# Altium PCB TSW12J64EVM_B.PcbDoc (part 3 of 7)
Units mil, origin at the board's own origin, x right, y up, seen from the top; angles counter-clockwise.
Board outline 8833 x 2680 mil, 10 copper layers (Top Layer L1, Gnd-Plane - L2, Signals - L3, Gnd-Plane - L4, Pwr Plane - L5, Signals - L6, Gnd-Plane - L7, Signals - L8, Gnd-Plane - L9, Bottom Layer - L10), stack 57.8 mil thick; 950 components, 533 nets, 2888 pads, 1732 vias.
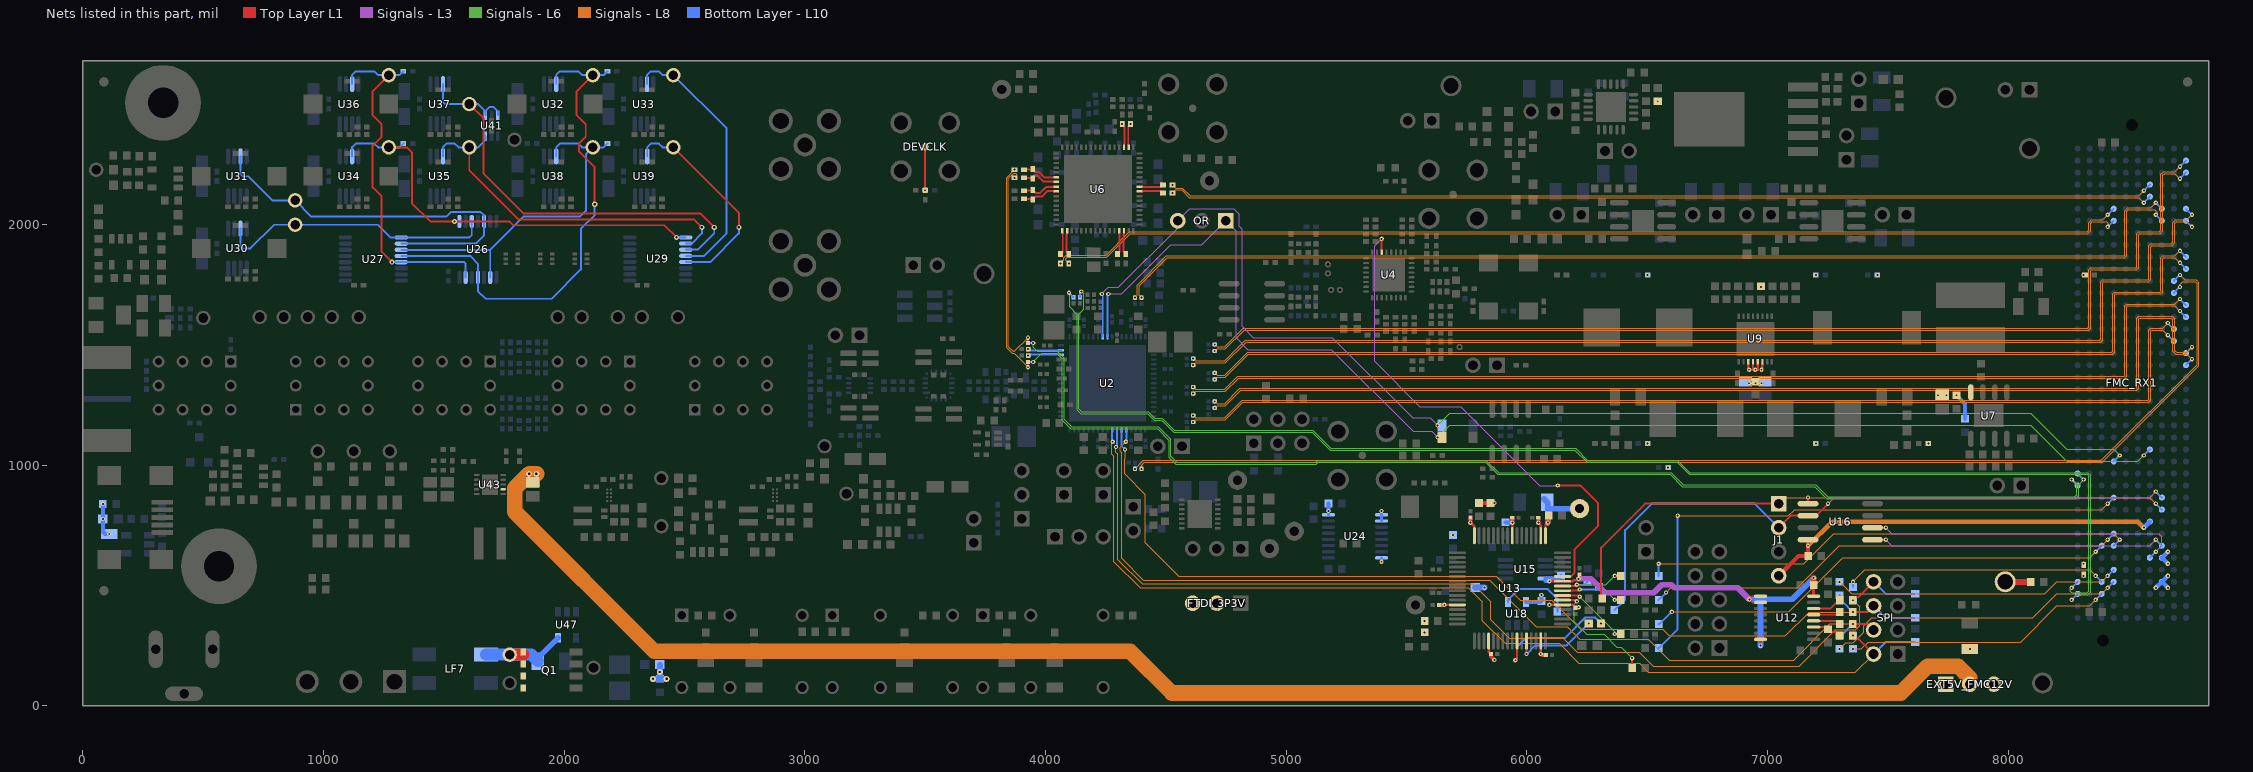
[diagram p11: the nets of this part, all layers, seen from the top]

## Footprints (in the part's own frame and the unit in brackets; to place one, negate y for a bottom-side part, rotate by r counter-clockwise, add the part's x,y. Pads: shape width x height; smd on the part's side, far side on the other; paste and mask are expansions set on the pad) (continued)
TSW-104-07-G-S [mm] "Samtec 100mil, 1x4, 230 mil above insulator"
  rect 1.65x1.65 hole 1.016 mask+0: 1(-3.81,0)
  round 1.65 hole 1.016 mask+0: 2(-1.27,0) 3(1.27,0) 4(3.81,0)
  silkscreen extent -6.1,-1.27 5.08,1.27, body extent -5.08,-1.27 5.08,1.27, height 8.38
VLS2012 [mm] "TDK"
  rect 0.65x2 smd: 1(-0.675,0) 2(0.675,0)
  silkscreen extent -0.15,-1.15 0.15,1.15, body extent -1.05,-1.05 1.05,1.05, height 1.2
WE-HC6 [mm] "Wurth Electronik recommended land pattern"
  rect 3.85x4 smd: 1(-3.825,0) 2(3.825,0)
  silkscreen extent -6.2,-6.2 6.2,6.2, body extent -5.77,-5.37 5.75,5.35, height 5
XFL4020 [mm] "Coilcraft XFL4020 7/18/12"
  rect 0.98x3.4 smd: 1(-1.181,0) 2(1.181,0)
  silkscreen extent -2.16,-2.16 2.16,2.16, body extent -2.15,-2.15 2.15,2.15, height 2.1
XTAL_ABM3 [mm] "Abracon recommended land pattern 12.28.10"
  rect 1.9x2.4 smd: 1(-2.05,0) 2(2.05,0)
  silkscreen extent -2.67,-1.78 2.67,1.78, body extent -2.6,-1.7 2.6,1.7, height 1.3
YFX0008ADAC [mm] "WCSP, 8-Leads, Body 1.645x0.855mm, Pitch 0.4mm"
  round 0.23 smd paste-0.13 mask+0.038: A1(-0.2,0.6) A2(0.2,0.6) B1(-0.2,0.2) B2(0.2,0.2) C1(-0.2,-0.2) C2(0.2,-0.2) D1(-0.2,-0.6) D2(0.2,-0.6)
  silkscreen extent -0.7,0.81 -0.53,0.99, body extent -0.45,-0.84 0.45,0.84, height 0.68

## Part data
1:1 2:1 5:1 AC DC: "Switch, Tactile, SPST-NO, 0.05A, 12V, SMD"
"1:1 Atten" "2:1 Atten" "5:1 Atten" 12V "AC COUPLED" "DC COUPLED" LD Status1 Status2 USB_PWR: "LED, Green, SMD"
1P8USB 3P3USB +5 +5V DPDT_1A DPDT_1B DPDT_2A DPDT_2B DPDT_3A DPDT_3B DPDT_4A DPDT_4B DPDT_5A DPDT_5B GND4 K1_Ax K1_Bx K2_Ax K2_Bx K3_Ax K3_Bx K4_Ax K4_Bx K5_Ax K5_Bx LD1 LD2 LO2_N LO2_P LO3_N LO3_P OFFSET TCRIT1 TCRIT2 TCRIT3 TP41_4 VIO_3P75_U19 VIO_3P75_U23 VIO_5V_DRV VIO_5V_LMC VIO_5V_LMH VIO_5V_LOGIC VIO_-1P25_U19 VIO_-1P25_U23 Vtune: "TEST POINT.  No entry in BOM."
1V2ADC_INT 1V2ADC_LDO 1V9ADC 1V9INT "5401 PD" "6401 PD" EXT_Vcmo J2 J3 "KC705 JTAG" LMK_INT LMK_LDO LMX_INT LMX_LDO PG_RX1 Tdiode VA12 VA19 Vbg VD12: "Header, TH, 100mil, 2x1, Gold plated, 230 mil above insulator"
3P3RX GND GND1 GND2 GND3 VADJ_RX: "Test Point, TH, Multipurpose, Black"
5VDC: "Connector, DC Jack 2.1X5.5 mm, TH"
C1 C77 C79 C239 C242 C253 C256 C272 C309: "CAP, CERM, 0.01uF, 25V, +/-10%, X7R, 0402"
C2 C8 C11 C94 C95 C96 C215 C216 C217 C218 C219 C220 C221 C222 C223 C224 C225 C226 C227 C261: "CAP, CERM, 0.1uF, 10V, +/-10%, X7R, 0402"
C3 C275: "CAP, TA, 10uF, 10V, +/-10%, 0.9 ohm, SMD"
C4 C5 C18 C19 C73 C85 C86 C87 C88 C89 C100 C103 C104 C105 C106 C107 C109 C110 C111 C112 C113 C114 C120 C121 C123 C124 C206 C207 C208 C209 C231 C235 C250 C251 C258 C259 C260 C273 C274 C295 C296 C310 C321 C322 C323 C324 C325 C326 C327 C328 C329 C330 C331 C332 C333 C334 C335 C336 C337 C338 C339 C340 C346 C347 C349 C350 C351 C352 C353 C354 C355 C384: "CAP, CERM, 0.1uF, 10V, +/-10%, X5R, 0402"
C7 C9 C10 C12 C13 C14 C15 C17 C20 C21 C22 C23 C26 C28 C29 C31 C41 C42 C43 C44 C45 C46 C47 C51 C52 C53 C54 C55 C56 C57 C58 C62 C63 C64 C65 C66 C67 C68 C69 C70 C71 C118 C119 C131 C132 C133 C134 C136 C140 C142 C214: library part Capacitor, "CAP, CERM, 0.1uF, 6.3V, X5R, 10%, 0201"
C16: "CAP, CERM, 4.7uF, 6.3V, +/-20%, X5R, 0402"
C24 C115 C210: "CAP, CERM, 0.1uF, 16V, +/-5%, X7R, 0603"
C25 C34 C38: "CAP, CERM, 100pF, 50V, +/-5%, C0G/NP0, 0603"
C27 C48 C59 C72: "CAP, TANT, 10uF, 10V, +/-20%, 2.5 ohm, 3528-21 SMD"
C30 C36: "CAP, CERM, 0.22uF, 6.3V, +/-20%, X5R, 0201"
C32 C33 C35 C37 C90 C91 C92 C93 C262 C263: "CAP, CERM, 4700pF, 10V, +/-10%, X5R, 0201"
C39 C40 C49 C50 C60 C61 C99 C125 C143 C205: "CAP, CERM, 1uF, 10V, +/-10%, X5R, 0603"
C74: "CAP, CERM, 100pF, 25V, +/-5%, C0G/NP0, 0402"
C75 C76 C83 C84 C245: "CAP, CERM, 47pF, 50V, +/-5%, C0G/NP0, 0402"
C78 C80 C254 C257: "CAP, CERM, 27pF, 50V, +/-5%, C0G/NP0, 0402"
C81 C82 C232 C236 C240 C243 C252 C255: "CAP, CERM, 1uF, 6.3V, +/-20%, X5R, 0402"
C97 C98 C116 C126 C129 C130 C144 C147 C148 C151 C153 C159 C164 C167 C176 C177 C185 C189 C191 C198 C199 C213 C277 C281 C283 C288 C290 C298 C300 C357 C359 C390 C392 C393 C396 C399 C402 C405 C407 C411 C416: "CAP, CERM, 0.1uF, 25V, +/-5%, X7R, 0603"
C102 C311 C312 C313 C314 C315 C316 C317 C318 C319 C320: "CAP, CERM, 0.01uF, 16V, +/-10%, X7R, 0402"
C108 C155 C201 C211: "CAP, CERM, 1uF, 16V, +/-10%, X5R, 0603"
C117 C149: "CAP, CERM, 330pF, 50V, +/-5%, C0G/NP0, 0603"
C122: "CAP, CERM, 10uF, 10V, +/-10%, X5R, 0805"
C127 C160: "CAP, CERM, 4.7uF, 10V, +/-10%, X5R, 0603"
C128 C161 C278 C408: "CAP, CERM, 0.01uF, 100V, +/-20%, X7R, 0603"
C135 C137: "CAP, CERM, 18pF, 50V, +/-5%, C0G/NP0, 0402"
C138 C212: "CAP, CERM, 100uF, 6.3V, +/-20%, X5R, 1206"
C139 C141 C150 C152 C158 C163 C165 C166 C171 C172 C186 C188 C190 C194 C195 C196 C197 C200 C202 C203 C204 C276 C280 C282 C289 C297 C299 C358 C391 C395 C398 C401 C404 C406 C410 C415: "CAP, CERM, 10uF, 10V, +/-10%, C0G/NP0, 0603"
C145 C146 C173 C184 C382 C383: "CAP, CERM, 10uF, 16V, +/-10%, X5R, 0805"
C154: "CAP, CERM, 10pF, 50V, +/-5%, C0G/NP0, 0603"
C156 C157: "CAP, CERM, 47uF, 6.3V, +/-20%, X5R, 1206"
C162: "CAP, CERM, 3300pF, 25V, +/-10%, X7R, 0603"
C168: "CAP, CERM, 0.22uF, 16V, +/-10%, X7R, 0603"
C169 C170: "CAP, CERM, 0.1uF, 6.3V, +/-10%, X5R, 0402"
C174 C175: "CAP, CERM, 0.027uF, 16V, +/-10%, X7R, 0603"
C178 C179: "CAP, CERM, 0.039uF, 25V, +/-10%, X7R, 0603"
C180 C181 C182 C183: "CAP, CERM, 22uF, 10V, +/-20%, X5R, 1206"
C187: "CAP, CERM, 560pF, 50V, +/-5%, C0G/NP0, 0603"
C192: "CAP, CERM, 4700pF, 16V, +/-10%, X7R, 0603"
C193: "CAP, TA, 47 µF, 10 V, +/- 10%, 0.25 ohm, SMD"
C228 C229: library part GRM155R71A104KA01D, "CAP CER 0.5PF 50V NP0 0402"
C230 C234 LF2: "CAP, CERM, 47pF, 50V, +/-5%, C0G/NP0, 0603"
C233 C237 C238 C241 C246 C248: "CAP, CERM, 4.7pF, 50V, +/-5%, C0G/NP0, 0402"
C244: "CAP, CERM, 560pF, 50V, +/-5%, C0G/NP0, 0402"
C247: "CAP, CERM, 2.2pF, 50V, +/-5%, C0G/NP0, 0402"
C249: "CAP, CERM, 22pF, 50V, +/-5%, C0G/NP0, 0402"
C264 C265 C270 C271 C301 C302 C307 C308: "CAP, CERM, 0.01uF, 25V, +/-20%, X7R, 0306"
C266 C267 C268 C269 C303 C304 C305 C306: "CAP, CERM, 2200pF, 50V, +/-20%, X7R, 0306"
C279: "CAP, CERM, 15 pF, 50 V, +/- 5%, C0G/NP0, 0603"
C284 C285 C418 C419: "CAP, CERM, 22 µF, 6.3 V, +/- 20%, X5R, 0603"
C286 C385 C417: "CAP, CERM, 10 pF, 50 V, +/- 5%, C0G/NP0, 0402"
C287 C356 C389: "CAP, CERM, 2.2 µF, 10 V, +/- 10%, X5R, 0603"
C291 C292: "CAP, CERM, 1 pF, 50 V, +/- 5%, C0G/NP0, 0402"
C293 C294: "CAP, CERM, 2.4 pF, 50 V, +/- 5%, C0G/NP0, 0402"
C341 C342 C343 C344 C345: "CAP, CERM, 1000 pF, 25 V, +/- 5%, C0G/NP0, 0402"
C360 C361 C362 C363 C364 C365 C366 C367 C368 C369 C413 C414: "CAP, TA, 1 µF, 16 V, +/- 20%, 9.3 ohm, SMD"
C370 C371 C372 C373 C374 C375 C376 C377 C378 C379 C380 C381 C403: library part Capacitor, "CAP, CERM, xxxF, xxV, [TempCo], xx%, [PackageReference]"
C386 C387 C388 C394 C397 C400: "CAP, CERM, 22 µF, 16 V, +/- 10%, X5R, 0805"
C409: "CAP, CERM, 22 pF, 50 V, +/- 5%, C0G/NP0, 0603"
D1 D7: "Diode, Schottky, 30 V, 0.5 A, SOD882"
D2 D4: "Diode, Ultrafast, 100V, 0.15A, SOD-123"
D3: "Diode, Dual Switching, Series, 10-mA, 7V"
D5 D6: "Diode, Schottky, 40V, 5A, SMC"
DEVCLK EXT_VCO LMKCLK OSCin: "Connector, SMA,Vertical, Thru hole w/SMT center pin"
EXT5V_FMC12V: "Header, TH, 100mil, 1x3, Gold plated, 230 mil above insulator"
F1: "Fuse, 2 A, 63 V, SMD"
FID1 FID2 FID3: "Fiducial mark.  There is nothing to buy or mount."
FL1 FL2 FL3: "Filter, LC, 0.2uF, 1806, SMT"
FMC_RX1: "Connector, Receptacle, 400-Pos (40x10), 50x50-mil Pitch, SMT"
FTDI_3P3V OR RSV "Ts ADD1" Vcmo: "Header, TH, 100mil, 3x1, Gold plated, 230 mil above insulator"
H3 H4: library part 1902C, "Standoff, Round, 3/16\"  x 1-3/16\"L #4-40 Aluminum"
H5 H6: "Machine Screw, Round, #4-40 x 1/4, Nylon, Philips panhead"
J1: "Header, TH, 100mil, 4x1, Gold plated, 230 mil above insulator"
K1 K2 K3 K4 K5: "Relay, DPDT (2 Form C), , 5 VDC, TH, K1 - K5 Body to be mounted approxiamtely 0.025 inches above PC board but cannot be in contact with the PC board"
K6 K7: "Relay, SPDT (1 Form C), 2A, 5 VDC, TH"
K8: "Relay, SPDT (1 Form C), 2 A, 5 VDC, TH"
L1 L27 L28 L29 L30 L31 L32 L33 L34: "0.25A Ferrite Bead, 1000 ohm @ 100MHz, SMD"
L2 L3 L4 L5 L19 L21 L22 L23: "1.5A Ferrite Bead, 330 ohm @ 100MHz, SMD"
L6 L9 L10 L13 L15 L16 L17 L18 L26: "6A Ferrite Bead, 26 ohm @ 100MHz, SMD"
L7 L14 L20 L24 L25 L35 L36 L40 L42 L43 L44 L45 L46 L47 L48 L50 L51 L52 L53 L54: "3A Ferrite Bead, 120 ohm @ 100MHz, SMD"
L8: "Inductor, Shielded Drum Core, Ferrite, 3uH, 3A, 0.024 ohm, SMD"
L11: "Inductor, Shielded Drum Core, Ferrite, 7uH, 4.35A, 0.03 ohm, SMD"
L12: "Inductor, Shielded Drum Core, Superflux, 5.5uH, 10A, 0.0112 ohm, SMD"
L37 L41: "Inductor, Shielded, Ferrite, 6.8 µH, 0.57 A, 0.498 ohm, SMD"
L38 L39: "Inductor, Wirewound, 5.6 nH, 0.9 A, 0.045 ohm, SMD"
L49: "Inductor, Shielded, Composite, 1 µH, 5.4 A, 0.01 ohm, SMD"
L55 L56: "Inductor, Wirewound, Ceramic, 3.9 nH, 2.2 A, 0.054 ohm, SMD"
LF1: "CAP, CERM, 3900pF, 25V, +/-5%, C0G/NP0, 0603"
LF3: "RES, 619 ohm, 1%, 0.1W, 0603"
LF7: "Coupled inductor, 5A, 0.01 ohm, SMD"
Logo1: library part ESD_Susceptible, "ESD Susceptible Symbol"
Logo2: library part TI_Logo, "Texas Instrument Corporate Signature"
Logo3: library part Pb-Free
Logo4: library part FCC_disclaimer, "FCC_disclaimer"
LOGO5: library part IEC_HotSurface, "IEC 61010-1 Hot Surface Warning"
NCO: "Header, TH, 100mil, 3x2, Gold plated, 230 mil above insulator"
"OFFSET ADJ": "Trimmer, 1k, 0.25W, SMT"
OR_T0 OR_T1: "LED, Orange, SMD"
Q1: "MOSFET, N-CH, 60 V, 172 A, SON 5x6mm"
Q2 Q3 Q4: "MOSFET, P-CH, 20 V, 0.83 A, SOT-563"
R1: "RES, 8.06k ohm, 1%, 0.063W, 0402"
R2 R10: "RES, 1.2k ohm, 5%, 0.063W, 0402"
R3 R11 R150 R243 R245: "RES, 1.0Meg ohm, 5%, 0.063W, 0402"
R4 R5 R6 R14 R15 R16 R105 R106 R107 R123 R130 R131 R187: "RES, 10.0k ohm, 1%, 0.1W, 0603"
R7 R8 R9 R18 R19 R20 R21 R22 R23: "RES, 0 ohm, 5%, 0.05W, 0201"
R12: "RES, 1.33k ohm, 1%, 0.063W, 0402"
R13: "RES, 3.30k ohm, 0.1%, 0.1W, 0603"
R17: "RES, 750 ohm, 5%, 0.1W, 0603"
R24 R144 R190 R234 R235 R236 R237 R238: "RES, 10.0k ohm, 1%, 0.063W, 0402"
R25 R26 R29 R36 R38 R43 R44 R48 R59 R60 R61 R62 R63 R64 R145 R146 R147 R148 R149 R160 R161 R178 R181 R233: "RES, 0 ohm, 5%, 0.063W, 0402"
R27 R28 R34 R35: "RES, 100 ohm, 1%, 0.063W, 0402"
R30 R153 R229 R230: "RES, 49.9 ohm, 1%, 0.063W, 0402"
R31 R32 R122: "RES, 1.3k ohm, 5%, 0.1W, 0603"
R33 R37: "RES, 3.3k ohm, 5%, 0.063W, 0402"
R39 R71 R80 R134: "RES, 1.0k ohm, 5%, 0.1W, 0603"
R40 R42 R73 R75 R83 R84 R92 R95: "RES, 0.002 ohm, 1%, 1W, 1206"
R41 R74: "RES, 10.7k ohm, 1%, 0.1W, 0603"
R45 R56 R112: "RES, 270 ohm, 5%, 0.1W, 0603"
R47: "RES, 2.32k ohm, 1%, 0.1W, 0603"
R49 R77: "RES, 4.64k ohm, 1%, 0.1W, 0603"
R50 R239 R240 R241: library part Resistor, "RES, xxx ohm, x%, xW, [PackageReference]"
R51 R165: "RES, 51 ohm, 5%, 0.063W, 0402"
R52 R53: "RES, 10 ohm, 5%, 0.1W, 0603"
R54 R55 R57 R58 R65 R68 R69 R109 R110 R111 R113 R114 R115 R117 R118 R119 R120 R121 R124 R125 R126 R127 R186: "RES, 100 ohm, 5%, 0.1W, 0603"
R66 R93: "RES, 1.00k ohm, 1%, 0.1W, 0603"
R67: "RES, 12.0k ohm, 1%, 0.1W, 0603"
R70: "RES, 10k ohm, 5%, 0.1W, 0603"
R72 R177: "RES, 95.3 k, 1%, 0.1 W, 0603"
R76: "RES, 22.1k ohm, 1%, 0.1W, 0603"
R78: "RES, 10.0 ohm, 1%, 0.1W, 0603"
R79: "RES, 732 ohm, 1%, 0.1W, 0603"
R81: "RES, 16.2k ohm, 1%, 0.1W, 0603"
R82: "RES, 7.87k ohm, 1%, 0.1W, 0603"
R85: "RES, 2.49k ohm, 1%, 0.1W, 0603"
R86 R87: "RES, 5.90k ohm, 1%, 0.1W, 0603"
R88 RR6: "RES, 4.99k ohm, 1%, 0.1W, 0603"
R89: "RES, 2.80k ohm, 1%, 0.1W, 0603"
R90: "RES, 402 ohm, 1%, 0.1W, 0603"
R91: "RES, 4.99k ohm, 1%, 0.063W, 0402"
R94 R251 R252 R253 R254 R255: "RES, 1.0k ohm, 5%, 0.25W, 1206"
R96: "RES, 357 ohm, 1%, 0.1W, 0603"
R97 R98 R101 R102: "RES, 12.4k ohm, 1%, 0.1W, 0603"
R99 R100 R103 R132 R142 R143 R151 R152 R259 R260 R261 R262 R263 R264 RR7: "RES, 0 ohm, 5%, 0.1W, 0603"
R104 R116 R128 R129: "RES, 24k ohm, 5%, 0.063W, 0402"
R108: "RES, 2.2k ohm, 5%, 0.1W, 0603"
R133 R170 R173 R242 R250 R256: "RES, 1.00k ohm, 1%, 0.063W, 0402"
R135: "RES, 2.10k ohm, 1%, 0.1W, 0603"
R136 R137 R138: "RES, 4.7k ohm, 5%, 0.1W, 0603"
R139 R140 R141: "RES, 2.0k ohm, 5%, 0.1W, 0603"
R154: "RES, 261, 1%, 0.063 W, 0402"
R156 R157: "RES, 127 ohm, 1%, 0.063W, 0402"
R158 R159: "RES, 82.5 ohm, 1%, 0.063W, 0402"
R162: "RES, 107 ohm, 1%, 0.063W, 0402"
R163 R164: "RES, 2.2k ohm, 5%, 0.063W, 0402"
R166 R167: "RES, 560, 5%, 0.063 W, 0402"
R168 R204: "RES, 365, 1%, 0.063 W, 0402"
R169 R203: "RES, 22.6, 1%, 0.063 W, 0402"
R171: "RES, 62.0 k, 1%, 0.1 W, 0603"
R172 R249: "RES, 30.1 k, 1%, 0.1 W, 0603"
R174 R257: "RES, 274 k, 1%, 0.063 W, 0402"
R175 R213 R214 R215 R216 R217 R218 R219 R220 R221 R222 R258: "RES, 100 k, 1%, 0.063 W, 0402"
R176: "RES, 5.23 k, 1%, 0.1 W, 0603"
R179 R180: "RES, 4.99, 1%, 0.063 W, 0402"
R182 R183 R188 R189: "RES, 2.00 k, 1%, 0.063 W, 0402"
R184 R185: "RES, 1.21 k, 1%, 0.063 W, 0402"
R191 R193 R200 R202: library part CRCW0402150RFKED, "RES, 150, 0.1%, 0.063 W, 0402"
R192 R201: library part CRCW040237R4FKED, "RES, 37.4, 0.1%, 0.063 W, 0402"
R194 R196 R197 R199: library part CRCW040275R0FKED, "RES, 75.0, 0.1%, 0.063 W, 0402"
R195 R198: library part CRCW0402121RFKED, "RES, 121, 0.1%, 0.063 W, 0402"
R205 R206: "RES, 15.0, 1%, 0.063 W, 0402"
R207 R208: "RES, 0, 5%, 0.063 W, 0402"
R209 R210: "RES, 127, 1%, 0.063 W, 0402"
R211 R212: "RES, 40.2 ohm, 1%, 0.063W, 0402"
R224 R225 R226 R227 R228: "RES, 10.0 k, 1%, 0.063 W, 0402"
R231: "RES, 60.4 k, 1%, 0.1 W, 0603"
R232: "RES, 39.2 k, 1%, 0.1 W, 0603"
R244: "RES, 110 k, 1%, 0.063 W, 0402"
R246: "RES, 80.6 k, 1%, 0.1 W, 0603"
R247: "RES, 25.5 k, 1%, 0.1 W, 0603"
R248: "RES, 43.2 k, 1%, 0.1 W, 0603"
S1: "SWITCH SLIDE SPST 4A PCB, TH"
SH-1V2ADC_INT_1_2 SH-1V2ADC_LDO_1_2 SH-1V9ADC_1_2 SH-1V9INT_1_2 SH-EXT5V_FMC12V_1_2 SH-FTDI_3P3V_1_2 SH-J2_1_2 SH-LMK_INT_1_2 SH-LMK_LDO_1_2 SH-LMX_INT_1_2 SH-LMX_LDO_1_2 SH-RSV_1_2 "SH-Ts ADD1_1_2" Vcmo_2_3: "Shunt, 100mil, Gold plated, Black"
SPI: "Header, TH, 100mil, 4x2, Gold plated, 230 mil above insulator"
T2: "Transformer, RF, 50 ohm, 10 to 4000 MHz, SMT"
TEMP: "LED, Red, SMD"
TMST+ TMST-: "Connector, TH, SMA"
U1: library part LMC6762AIMX, "Dual Micro-Power Rail-to-Rail Input CMOS Comparator with Push-Pull Output, 8-pin Narrow SOIC"
U2: library part ADC12X3500RFLQNOPB, "ADC12J4000RLY Ultra-Wideband RF Sampling Subsystem, RLY0068A"
U3: "Dual Remote Diode and Local Temperature Sensor with SMBus Interface and TruTherm Technology, 14-pin LLP, Pb-Free"
U4: "Integer-N/Fractional-N PLL with Integrated VCO, RHB0032E"
U5 U8: "Micropower 800mA Low Noise \"Ceramic Stable\" Adjustable Voltage Regulator for 1V to 5V Applications, 8-pin PSOP, Pb-Free"
U6: "Low-Noise Clock Jitter Cleaner with Dual Loop PLLs, NKD0064A"
U7: "3-A OUTPUT SINGLE SYNCRONOUS STEP DOWN SWITCHER WITH INTEGRATED FET(SWIFT), DDA0008B"
U9: "Dual 2A, 500kHz Wide Input Range Buck Regulator, 16-pin LLP, Pb-Free"
U10: "3.0A Low Dropout Linear Regulator with Programmable Soft-Start, RGW0020A"
U11: "3A Fast-Transient Response Adjustable Low-Dropout Linear Voltage Regulator, 5-pin TO-263 Thin, Pb-Free"
U12 U24: "4-BIT DUAL-SUPPLY BUS TRANSCEIVER WITH CONFIGURABLE VOLTAGE TRANSLATION AND 3-STATE OUTPUTS, PW0016A"
U13: "Quad High Speed USB to Multipurpose UART/MPSSE IC"
U14: "300-mA, Low-IQ, Low-Dropout Regulator, DBV0005A"
U15: "1K, 64x16-bit, 2.5V Microwire Serial EEPROM, 8-Pin MSOP, Industrial Temperature"
U16: "64Kbit, 400kHz, 4.5V, I2C Serial EEPROM, 8-Pin SOIC 208mil, Commercial Temperature, Tape and Reel"
U17: "Divide-by-2 Divider"
U18: "IC, Single Bus Buffer Gate With 3-States Output"
U19: library part LMH5401RMS, "8GHz Ultra Wideband Fully Differential Amplifier, RMS0014A"
U20 U45: "Single Output High PSRR LDO, 200 mA, Adjustable 1.22 to 5.5 V Output, 2.7 to 5.5 V Input, 6-pin SOT-23 (DBV), -40 to 85 degC, Green (RoHS & no Sb/Br)"
U21 U48: "SIMPLE SWITCHER Buck-Boost Converter For Negative Output Voltage in uSMD, YFX0008ADAC"
U22 U42: "Single Output LDO, 200 mA, Adjustable -10 to -1.2 V Output, -10 to -2.7 V Input, 5-pin SOT-23 (DBV), -40 to 125 degC, Green (RoHS & no Sb/Br)"
U23: "5 GHz Ultra Wideband Digital Variable Gain Amplifier, RMZ0016A"
U25: "Precision, Low Noise, Low Iq Operational Amplifier, 2.2 to 5.5 V, -40 to 125 degC, 5-pin SOT23 (DCK0005A), Green (RoHS & no Sb/Br)"
U26: "High-Speed CMOS Logic Hex Inverting Schmitt Triggers, PW0014A"
U27 U29: "7- bit Integrated Motor and Relay Driver, PW0016A"
U30 U31 U32 U33 U34 U35 U36 U37 U38 U39: "CMOS Timer, 8-pin Mini SOIC, Pb-Free"
U40: "High-Speed, Closed-Loop Buffer, DBV0005A"
U41: "IC, Configurable Multiple-Function Gate"
U43: "High Input Voltage Buck-Boost Converter with 2 A Switch Current, DSC0010E"
U44: "Cap-Free, NMOS, 250mA Low Dropout Regulator with Reverse Current Protection, DBV0005A"
U47: "OVERVOLTAGE PROTECTION CONTROLLER, DBV0005A"
USB: "MINI USB 2.0 SMT TYPE AB 5 CONTACTS R/A, SMD"
uWIRE: "Connector, 100mil Shrouded, 5x2, High-Temperature, Gold, TH"
VIN: "Connector, SMT, End launch SMA 50 ohm"
Y1: "OSC 100.0000MHZ 3.3V +-25PPM SMD"
Y2: "Crystal, 12Mhz, 18pF, SMD"
ZZ2 ZZ3 ZZ4: library part AssemblyNote

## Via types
v1: diameter 18, hole 8, Top Layer L1 to Bottom Layer - L10, tented both sides, 1096 vias
v2: diameter 21.46, hole 10, Top Layer L1 to Bottom Layer - L10, tented both sides, 266 vias
v3: diameter 25, hole 10, Top Layer L1 to Bottom Layer - L10, tented both sides, 154 vias
v4: diameter 19.68, hole 7.87, Top Layer L1 to Bottom Layer - L10, 103 vias
v5: diameter 18, hole 8, Top Layer L1 to Bottom Layer - L10, tented bottom, 42 vias
v6: diameter 18, hole 8, Top Layer L1 to Bottom Layer - L10, tented top, 24 vias
v7: diameter 18, hole 8.01, Top Layer L1 to Bottom Layer - L10, tented both sides, 16 vias
v8: diameter 18, hole 8.01, Top Layer L1 to Bottom Layer - L10, tented bottom, 16 vias
v9: diameter 25.98, hole 12.99, Top Layer L1 to Bottom Layer - L10, tented top, 8 vias
v10: diameter 19.68, hole 7.87, Top Layer L1 to Bottom Layer - L10, tented top, 5 vias
v11: diameter 126, hole 106, Top Layer L1 to Bottom Layer - L10, tented top, 2 vias

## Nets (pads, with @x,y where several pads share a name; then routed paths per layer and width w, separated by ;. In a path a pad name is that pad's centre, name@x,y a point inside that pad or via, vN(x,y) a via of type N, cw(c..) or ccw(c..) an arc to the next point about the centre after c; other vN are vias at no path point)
1P8V_USB: 1P8USB.1 C133.1 C134.1 C136.1 C200.1 C212.2 U13.12 U13.37 U13.49 U13.64 | length 608
  Top Layer L1 w10: v1(5656.5,419.1) U13.12@5710.97,419.1 ; v1(5765,760.97) 5781.83,744.14 U13.64@5781.83,706.5 ; U13.49@6077.11,706.5 6077.11,751.13 v1(6086.95,760.97) ; v1(6093.51,419.1) U13.37@6147.98,419.1 6190.83,419.1 C134.1@6202.44,407.49 6204.22,409.26 v1(6215,409.26)
  Top Layer L1 w16.5: C133.1@5635.44,419.1 v1(5656.5,419.1) ; v1(5765,760.97) C136.1@5765,782.03
  Top Layer L1 w24: v1(6086.95,760.97) 6086.95,785.96 C200.1@6090.7,789.7
  Bottom Layer - L10 w24: C212.2@6070,860.09 C212.2@6084.09,846 ; v1(6086.95,760.97) C212.2@6086.95,843.13 ; C212.2@6086.95,819 1P8USB.1@6219,819
3P3V_FTDI: C97.1 C118.1 C119.1 C129.1 C131.1 C132.1 C205.1 C213.1 C214.1 FTDI_3P3V.2 L24.1 L25.1 R66.2 R105.2 R106.2 R107.2 U12.1 U12.2 U12.8 U12.16 U13.20 U13.31 U13.42 U13.50 U13.56 U15.8 U18.5 U24.1 U24.2 U24.8 U24.16 USB_PWR.1 | length 2364.2
  Top Layer L1 w8: U12.2@6970.76,429.5 6936.79,429.5 v1(6924,442.3) 6936.8,455.1 U12.1@6970.76,455.1
  Top Layer L1 w10: U13.20@5840.89,269.5 5840.89,224.87 C118.1@5850.73,215.03 ; U13.56@5939.31,706.5 v1(5939.31,760.97) ; v1(6047.58,760.97) 6057.42,751.13 U13.50@6057.42,706.5 ; v1(6057.43,215.03) U13.31@6057.42,269.5 ; v1(6093.51,517.53) U13.42@6147.98,517.53 6190.83,517.53 6194.14,520.84 6208.47,520.84 v1(6215,527.37)
  Top Layer L1 w13: v1(6970.76,250) U12.8@6970.76,275.96 ; U12.16@7191.24,455.1 C129.1@7191.24,502.06
  Top Layer L1 w16: v1(6215,527.37) 6218.44,530.82 C131.1@6218.44,545.43
  Top Layer L1 w16.5: R107.2@5800.2,842.56 v1(5865,842.56) ; C118.1@5850.73,215.03 5850.73,204.27 v1(5865,190) ; v1(5939.31,760.97) C132.1@5939.31,781.24 ; v1(6047.58,760.97) C214.1@6047.58,781.24 ; v1(6057.43,215.03) 6062.43,210.03 C119.1@6078.48,210.03
  Top Layer L1 w24: C129.1@7191.24,502.06 v1(7191.24,530.79)
  Signals - L3 w24: v1(6215,527.37) 6266.63,527.37 6324,470 6527,470 6560,503 6600,503 6613,490 6876.3,490 v1(6924,442.3)
  Bottom Layer - L10 w13: U24.16@5175.57,793.57 v1(5175.57,809.46) ; v1(5396.05,598.54) U24.8@5396.05,614.43 ; U24.2@5396.05,767.98 U24.1@5396.05,793.57 v1(5396.05,809.46)
  Bottom Layer - L10 w16.5: R105.2@5911.32,762.56 5912.91,760.97 v1(5939.31,760.97) ; U18.5@5996.07,430.85 6055.59,430.85 C213.1@6060,435.25 v1(6060,460) ; v1(6093.51,517.53) 6076.68,517.53 U15.8@6076.68,528.61 6131.17,528.61 C205.1@6142,539.44
  Bottom Layer - L10 w18: v1(5175.57,809.46) C97.1@5175.57,840
  Bottom Layer - L10 w24: L24.1@5784.5,491 v1(5824,491) ; v1(6924,442.3) 6970.76,442.3 ; v1(6970.76,250) 6970.76,442.3 ; v1(7191.24,530.79) 7102.75,442.3 6970.76,442.3
  other v1: 5574.91,304.73 5574.91,351.73 5692.56,709.56
3P3V_RX: 3P3RX.1 R132.1 | length 105.4
  Top Layer L1 w25: 3P3RX.1@7987,515 R132.1@8092.44,515
3P3V_USB: C138.1 C210.1 FTDI_3P3V.3 L26.2 | length 146.8
  Bottom Layer - L10 w16.5: v1(83.74,839) 83.74,722.26 92.46,713.54 v1(110.24,713.54)
  other v1: 83.74,775.86
3P3VAUX: C143.1 FMC_RX1.D32 J1.4 U16.8 | length 1706.1
  Top Layer L1 w18: J1.4@7046,540 7128,622 C143.1@7168.14,622 U16.8@7168.14,690
  Signals - L8 w18: v1(7168.14,665) 7268.14,765 8538,765 v5(8563,740)
  Bottom Layer - L10 w18: v5(8563,740) FMC_RX1.D32@8588,765
5.0V_IN: +5V.1 F1.2 LF7.3 Q1.5 Q1.6 Q1.7 Q1.8 U47.5 | length 415.1
  Top Layer L1 w50: +5V.1@1774,212.6 Q1.5@1830.7,212.6
  Bottom Layer - L10 w23.62: F1.2@1890.91,185.3 1890.91,198.7 U47.5@1974.5,282.28
  Bottom Layer - L10 w50: LF7.3@1675.46,212.6 +5V.1@1774,212.6 1863.61,212.6 F1.2@1890.91,185.3
5P0_12P0V_INT: C94.1 C145.1 C146.1 C147.1 C167.1 C173.1 C184.1 C220.2 C221.2 C222.2 C223.2 C225.2 C226.2 C227.2 C261.1 C382.1 C383.1 EXT5V_FMC12V.2 R70.1 R78.1 R79.2 R94.2 U7.8 U9.11 U9.12 U9.13 U9.14 U43.2 | length 7092.2
  Top Layer L1 w10: v1@6919.47,1396 U9.11@6919.47,1429.51 ; 6939.16,1396 U9.12@6939.16,1429.51 ; 6958.84,1396 U9.13@6958.84,1429.51 ; v1@6978.53,1396 U9.14@6978.53,1429.51
  Top Layer L1 w18: v1(6923.47,1340) v1(6974.53,1340)
  Top Layer L1 w25: C383.1@1854.94,929.53 v3(1854.94,963.68) ; C383.1@1885.06,929.53 v3(1885.06,963.68)
  Signals - L8 w64.96: v3(1885.06,963.68) v3(1854.94,963.68) 1795,903.74 1795,806 2374,227 ; 2377,226 4352,226 4525,53 7553,53 7665,165 7791,165 7840,116 EXT5V_FMC12V.2@7840,90
  Bottom Layer - L10 w18: v1@7785,1289.56 7820.19,1254.37 R70.1@7820.19,1192.41
  Bottom Layer - L10 w25: C382.1@1854.94,929.53 v3(1854.94,963.68) ; C382.1@1885.06,929.53 v3(1885.06,963.68)
  other v1: 7840,235.85 8313,590 6586.69,990 6501.69,1090 7200.31,1090 7667.69,1090 7708,1290 7744,1290 7785,1290 6949,1340 6923.47,1396 6949,1396 6974.53,1396 6973,1740 6501.69,1790 7200.31,1790 7455.69,1790 8313,1790 6543.68,2511.44
5VDC: C194.1 EXT5V_FMC12V.1 L17.2 | length 113
  Bottom Layer - L10 w25: v3(2369.25,111.94) C194.1@2397.5,111.94 ; L17.2@2397.5,168.43 v3(2397.5,140.19) C194.1@2397.5,111.94 ; v3(2425.74,111.94) C194.1@2397.5,111.94
12P0V_RX: C94.2 EXT5V_FMC12V.3 FMC_RX1.C35 FMC_RX1.C37 | length 176.8
  Bottom Layer - L10 w18: v1(8613,490) FMC_RX1.C37@8638,515 ; v5(8663,490) FMC_RX1.C37@8638,515 ; v5(8663,540) FMC_RX1.C37@8638,515 ; v5(8663,590) FMC_RX1.C35@8638,615 v5(8663,640)
  other v1: 8313,540
ADC_OR_T0: D2.2 FMC_RX1.G27 OR.3 U2.25 | length 5339.6
  Signals - L3 w4: v1(4234.04,1710.8) 4261.24,1738 4303,1738 4549.5,1984.5 OR.3@4549.5,2015 4599.5,2065 4782,2065 4804,2043 4804,1993 4817,1980 4817,1577 4864,1530 5191,1530 5525,1196 5598,1196 v1(5629,1165)
  Signals - L6 w4: v1(5629,1165) 5679,1215 8093,1215 8243,1065 8438,1065 v5(8463,1040)
  Bottom Layer - L10 w8: v1(4234.04,1710.8) 4237.7,1707.14 U2.25@4237.7,1532.91 ; FMC_RX1.G27@8438,1015 v5(8463,1040)
ADC_OR_T1: D4.2 FMC_RX1.D26 OR.1 U2.26 | length 5368.5
  Signals - L3 w4: v1(4261.05,1710.8) 4315.8,1710.8 4520,1915 4649.5,1915 OR.1@4749.5,2015 4792,1972.5 4792,1529 4841,1480 5188,1480 5528,1140 5604,1140 v1(5629,1115)
  Signals - L6 w4: v1(5629,1115) 5679,1165 8093,1165 8243,1015 8538,1015 v5(8563,1040)
  Bottom Layer - L10 w8: U2.26@4257.39,1532.91 4257.39,1707.14 v1(4261.05,1710.8) ; v5(8563,1040) FMC_RX1.D26@8588,1065
ADC_SCLK: R58.1 R109.1 R141.2 SPI.8 U2.58 | length 4351.5
  Top Layer L1 w8: v1(7354.56,438.5) 7367.06,451 7376,451 SPI.8@7440,515
  Signals - L8 w4: v1(4292.76,1075) 4292.76,1054.24 4300,1047 4300,607 4401,506 5775,506 5849,432 5849,358 5927,280 6152,280 6209,223 6466,223 6524,165 7131,165 7282,316 7366,316 7382,332 7382,411.06 v1(7354.56,438.5)
  Bottom Layer - L10 w8: v1(4292.76,1075) 4296.76,1079 U2.58@4296.76,1147.09 ; SPI.8@7440,515 7490,465 R141.2@7613.44,465
ADC_SCSB: R54.1 R118.1 R139.2 SPI.2 U2.59 | length 4287.8
  Top Layer L1 w8: v1(7354.56,291.5) 7367.06,279 7376,279 SPI.2@7440,215
  Signals - L8 w4: v1(4279.19,1097) 4276,1093.81 4276,1044 4284,1036 4284,599 4393,490 5757,490 5814.75,432.25 5814.75,354.25 5910,259 6134,259 6216,177 6468,177 6505,140 7365,140 SPI.2@7440,215
  Bottom Layer - L10 w8: U2.59@4277.07,1147.09 4277.07,1099.12 v1(4279.19,1097) ; SPI.2@7440,215 7490,265 R139.2@7613.44,265
ADC_SDI: R57.1 R111.1 R140.2 SPI.6 U2.57 | length 4037.1
  Top Layer L1 w8: v1(7354.56,389.5) 7414.5,389.5 SPI.6@7440,415
  Signals - L8 w4: v1(4330.44,1065) 4330.44,1026.44 4329,1025 4329,963 4414.28,877.72 4414.28,676.72 4553,538 5872,538 5972,438 6103,438 6224,317 6564,317 6591,290 7073,290 7172.5,389.5 v1(7354.56,389.5)
  Bottom Layer - L10 w8: U2.57@4316.44,1147.09 4316.44,1079 v1(4330.44,1065) ; R57.1@7299.44,459.88 7312,447.32 7312,432.06 v1(7354.56,389.5) ; SPI.6@7440,415 7490,365 R140.2@7613.44,365
ADC_SDO: R55.1 R110.1 SPI.4 U2.56 | length 3994.1
  Top Layer L1 w8: v1(7354.56,340.5) 7414.5,340.5 SPI.4@7440,315
  Signals - L8 w4: v1(4334,1097) 4311,1074 4311,1057 4316,1052 4316,613 4407,522 5845,522 6038,329 6167,329 6219,277 6505,277 6592,190 7108.36,190 7258.86,340.5 v1(7354.56,340.5)
  Bottom Layer - L10 w8: v1(4334,1097) 4336.13,1099.12 U2.56@4336.13,1147.09 ; R55.1@7299.44,291.5 7305.56,291.5 v1(7354.56,340.5)
CLK0_N: R63.1 U6.2 | length 101.6
  Top Layer L1 w8: U6.2@4089.61,1973.77 4089.61,1961.77 4087.76,1959.93 4087.76,1885.68 R63.1@4096.76,1876.68
CLK0_P: R64.1 U6.1 | length 101.6
  Top Layer L1 w8: R64.1@4062.76,1876.68 4071.76,1885.68 4071.76,1959.93 4069.92,1961.77 U6.1@4069.92,1973.77
CLK3_N: R61.1 U6.14 | length 101.6
  Top Layer L1 w8: U6.14@4325.83,1973.77 4325.83,1961.77 4323.99,1959.93 4323.99,1885.68 R61.1@4332.98,1876.69
CLK3_P: R62.1 U6.13 | length 101.6
  Top Layer L1 w8: R62.1@4298.98,1876.69 4307.98,1885.68 4307.98,1959.93 4306.14,1961.77 U6.13@4306.14,1973.77
CLK4_N: R59.1 U6.25 | length 101.6
  Top Layer L1 w8: U6.25@4390.79,2156.84 4402.79,2156.84 4404.63,2155 4478.87,2155 R59.1@4487.87,2164
CLK4_P: R60.1 U6.24 | length 101.6
  Top Layer L1 w8: U6.24@4390.79,2137.16 4402.79,2137.16 4404.63,2139 4478.87,2139 R60.1@4487.87,2130
CLK10_N: R160.1 R167.2 U6.55 | length 150.5
  Top Layer L1 w8: R160.1@3910.47,2193.37 3944.56,2193.37 R167.2@3947.24,2190.68 3958.93,2202.37 3966.05,2202.37 3990.05,2178.37 4030.49,2178.37 4032.33,2176.53 U6.55@4044.33,2176.53
CLK10_P: R161.1 R167.1 U6.54 | length 150.5
  Top Layer L1 w8: R161.1@3910.47,2227.37 3944.56,2227.37 R167.1@3947.24,2230.05 3958.93,2218.37 3972.68,2218.37 3996.68,2194.37 4030.49,2194.37 4032.33,2196.21 U6.54@4044.33,2196.21
CLK11_N: R43.1 R166.2 U6.57 | length 150.5
  Top Layer L1 w8: R43.1@3910.47,2106 3944.56,2106 R166.2@3947.24,2103.31 3958.93,2115 3984.68,2115 4008.68,2139 4030.49,2139 4032.33,2137.16 U6.57@4044.33,2137.16
CLK11_P: R44.1 R166.1 U6.56 | length 150.5
  Top Layer L1 w8: R44.1@3910.47,2140 3944.56,2140 R166.1@3947.24,2142.68 3958.93,2131 3978.05,2131 4002.05,2155 4030.49,2155 4032.33,2156.84 U6.56@4044.33,2156.84
CLKIN1_N: C112.1 C123.1 U6.35 | length 101.6
  Top Layer L1 w8: v6(4318.67,2417.32) 4327.67,2408.32 4327.67,2334.07 4325.83,2332.23 U6.35@4325.83,2320.23
CLKIN1_P: C113.1 C114.2 U6.34 | length 101.6
  Top Layer L1 w8: U6.34@4345.51,2320.23 4345.51,2332.23 4343.67,2334.07 4343.67,2408.32 v6(4352.67,2417.32)
D0_N: C9.1 FMC_RX1.C6 | length 4573.1
  Signals - L8 w4: v7(4371.84,1695.8) 4381.34,1705.3 4381.34,1747.83 4502.5,1869 8480.69,1869 8484,1872.31 8484,2057.31 8495.69,2069 8592,2069 v8(8613,2090)
  Bottom Layer - L10 w8: v8(8613,2090) FMC_RX1.C6@8638,2065
D0_P: C7.1 FMC_RX1.C7 | length 4573.3
  Signals - L8 w4: v7(4398.84,1695.8) 4389.34,1705.3 4389.34,1744.52 4505.82,1861 8484,1861 8492,1869 8492,2054 8499,2061 8608,2061 8618,2051 8618,2045 v8(8613,2040)
  Bottom Layer - L10 w8: v8(8613,2040) FMC_RX1.C7@8638,2015
D1_N: C12.1 FMC_RX1.A2 | length 4715.6
  Signals - L8 w4: v7(4703.19,1501.14) 4712.69,1491.64 4744.31,1491.64 4821.68,1569 8330.69,1569 8334,1572.31 8334,1811 8342,1819 8530.69,1819 8534,1822.31 8534,1961 8542,1969 8627,1969 8634,1976 8634,2207.31 8645.69,2219 8692,2219 v8(8713,2240)
  Bottom Layer - L10 w8: v8(8713,2240) FMC_RX1.A2@8738,2265
D1_P: C10.1 FMC_RX1.A3 | length 4715.6
  Signals - L8 w4: v7(4703.19,1474.14) 4712.69,1483.64 4747.63,1483.64 4824.99,1561 8334,1561 8342,1569 8342,1807.69 8345.31,1811 8534,1811 8542,1819 8542,1957.69 8545.31,1961 8630.31,1961 8642,1972.69 8642,2204 8649,2211 8692,2211 v8(8713,2190)
  Bottom Layer - L10 w8: v8(8713,2190) FMC_RX1.A3@8738,2215
D2_N: C14.1 FMC_RX1.A6 | length 4709.4
  Signals - L8 w4: v7(4613.19,1442.08) 4622.69,1432.58 4744.31,1432.58 4830.73,1519 8380.69,1519 8384,1522.31 8384,1761 8392,1769 8580.69,1769 8584,1772.31 8584,1911 8592,1919 8677,1919 8684,1926 8684,2007.31 8695.69,2019 8742,2019 v8(8763,2040)
  Bottom Layer - L10 w8: FMC_RX1.A6@8738,2065 v8(8763,2040)
D2_P: C13.1 FMC_RX1.A7 | length 4709.4
  Signals - L8 w4: v7(4613.19,1415.08) 4622.69,1424.58 4747.63,1424.58 4834.05,1511 8384,1511 8392,1519 8392,1757.69 8395.31,1761 8584,1761 8592,1769 8592,1907.69 8595.31,1911 8680.31,1911 8692,1922.69 8692,2004 8699,2011 8742,2011 v8(8763,1990)
  Bottom Layer - L10 w8: FMC_RX1.A7@8738,2015 v8(8763,1990)
D3_N: C17.1 FMC_RX1.A10 | length 4484.1
  Signals - L8 w4: v7(4703.19,1383.03) 4712.69,1373.53 4744.31,1373.53 4839.79,1469 8430.69,1469 8434,1472.31 8434,1711 8442,1719 8630.69,1719 8634,1722.31 8634,1861 8642,1869 8692,1869 v8(8713,1890)
  Bottom Layer - L10 w8: v8(8713,1890) FMC_RX1.A10@8738,1865
D3_P: C15.1 FMC_RX1.A11 | length 4484.1
  Signals - L8 w4: v7(4703.19,1356.03) 4712.69,1365.53 4747.63,1365.53 4843.1,1461 8434,1461 8442,1469 8442,1707.69 8445.31,1711 8634,1711 8642,1719 8642,1857.69 8645.31,1861 8692,1861 v8(8713,1840)
  Bottom Layer - L10 w8: v8(8713,1840) FMC_RX1.A11@8738,1815
D4_N: C21.1 FMC_RX1.A14 | length 4463.8
  Signals - L8 w4: v7(4613.19,1323.97) 4622.69,1314.47 4744.31,1314.47 4798.84,1369 8480.69,1369 8484,1372.31 8484,1661 8492,1669 8692,1669 v8(8713,1690)
  Bottom Layer - L10 w8: v8(8713,1690) FMC_RX1.A14@8738,1665
D4_P: C20.1 FMC_RX1.A15 | length 4463.8
  Signals - L8 w4: v7(4613.19,1296.97) 4622.69,1306.47 4747.63,1306.47 4802.15,1361 8484,1361 8492,1369 8492,1657.69 8495.31,1661 8692,1661 v8(8713,1640)
  Bottom Layer - L10 w8: v8(8713,1640) FMC_RX1.A15@8738,1615
D5_N: C23.1 FMC_RX1.A18 | length 4566.6
  Signals - L8 w4: v7(4703.19,1264.92) 4712.69,1255.42 4744.31,1255.42 4807.9,1319 8530.69,1319 8534,1322.31 8534,1611 8542,1619 8680.31,1619 8692,1607.31 8692,1476 8699,1469 8742,1469 v8(8763,1490)
  Bottom Layer - L10 w8: FMC_RX1.A18@8738,1465 v8(8763,1490)
D5_P: C22.1 FMC_RX1.A19 | length 4566.6
  Signals - L8 w4: v7(4703.19,1237.92) 4712.69,1247.42 4747.63,1247.42 4811.21,1311 8534,1311 8542,1319 8542,1607.69 8545.31,1611 8677,1611 8684,1604 8684,1472.69 8695.69,1461 8742,1461 v8(8763,1440)
  Bottom Layer - L10 w8: FMC_RX1.A19@8738,1415 v8(8763,1440)
D6_N: C28.1 FMC_RX1.B16 | length 4421.3
  Signals - L8 w4: v7(4613.19,1205.86) 4622.69,1196.36 4744.31,1196.36 4816.95,1269 8580.69,1269 8584,1272.31 8584,1561 8592,1569 8642,1569 v8(8663,1590)
  Bottom Layer - L10 w8: v8(8663,1590) FMC_RX1.B16@8688,1565
D6_P: C26.1 FMC_RX1.B17 | length 4421.3
  Signals - L8 w4: v7(4613.19,1178.86) 4622.69,1188.36 4747.63,1188.36 4820.27,1261 8584,1261 8592,1269 8592,1557.69 8595.31,1561 8642,1561 v8(8663,1540)
  Bottom Layer - L10 w8: v8(8663,1540) FMC_RX1.B17@8688,1515
D7_N: C31.1 FMC_RX1.B12 | length 5052
  Signals - L8 w4: v7(4398.84,984.2) 4398.84,999.89 4410.15,1011.2 8389.86,1011.2 8792,1413.34 8792,1757.31 8780.31,1769 8734,1769 v8(8713,1790)
  Bottom Layer - L10 w8: FMC_RX1.B12@8688,1765 v8(8713,1790)
D7_P: C29.1 FMC_RX1.B13 | length 5051.9
  Signals - L8 w4: v7(4371.84,984.2) 4406.84,1019.2 8386.54,1019.2 8784,1416.66 8784,1754 8777,1761 8725,1761 8713,1749 v8(8713,1740)
  Bottom Layer - L10 w8: FMC_RX1.B13@8688,1715 v8(8713,1740)
DEV_CLK_N: C263.2 R160.2 | length 898.6
  Top Layer L1 w8: C263.2@3927.57,1507.44 v1(3927.57,1529.49)
  Signals - L8 w4: v1(3871.1,2193.37) 3880.23,2202.49 3880.23,2208 3875.85,2212.37 3867.41,2212.37 3846,2190.96 3846,1491.01 3865.06,1471.95 3870.03,1471.95 v1(3927.57,1529.49)
DEV_CLK_P: C262.2 R161.2 | length 898.7
  Top Layer L1 w8: v1(3927.57,1406.41) C262.2@3927.57,1428.47
  Signals - L8 w4: v1(3871.1,2227.37) 3838,2194.27 3838,1487.7 3861.75,1463.95 3870.03,1463.95 v1(3927.57,1406.41)
DEVCLK: C87.2 C89.1 DEVCLK.1 R165.2 | length 180.3
  Top Layer L1 w8: v1(3500.06,2141.68) DEVCLK.1@3500.06,2322
DEVCLK_N: C33.1 C36.1 C93.1 C263.1 U2.16 | length 139.9
  Bottom Layer - L10 w8: v1(3927.57,1481.45) 3933.07,1475.95 4062.63,1475.95 U2.16@4064.47,1477.8
DEVCLK_P: C30.1 C32.1 C92.1 C262.1 U2.15 | length 139.9
  Bottom Layer - L10 w8: v1(3927.57,1454.45) 3933.07,1459.95 4062.63,1459.95 U2.15@4064.47,1458.11
DEVCLKARX_N: FMC_RX1.D5 R60.2 | length 4098.5
  Signals - L8 w4: v1(4527.24,2130) 4540.25,2143 4565.06,2143 4597.06,2111 8542,2111 v5(8563,2090)
  Bottom Layer - L10 w8: v5(8563,2090) FMC_RX1.D5@8588,2115
DEVCLKARX_P: FMC_RX1.D4 R59.2 | length 4098.4
  Signals - L8 w4: v1(4527.25,2164) 4540.24,2151 4568.37,2151 4600.38,2119 8542,2119 v5(8563,2140)
  Bottom Layer - L10 w8: v5(8563,2140) FMC_RX1.D4@8588,2165
DEVCLKBRX_N: FMC_RX1.G7 R63.2 | length 4494.7
  Signals - L8 w4: v1(4096.76,1837.31) 4083.76,1850.32 4083.76,1858.13 4089.95,1864.32 4255.32,1864.32 4352,1961 8330.31,1961 8342,1972.69 8342,2004 8349,2011 8408,2011 8418,2001 8418,1995 v5(8413,1990)
  Bottom Layer - L10 w8: v5(8413,1990) FMC_RX1.G7@8438,2015
DEVCLKBRX_P: FMC_RX1.G6 R64.2 | length 4494.4
  Signals - L8 w4: v1(4062.76,1837.32) 4075.76,1850.32 4075.76,1861.45 4086.63,1872.32 4252,1872.32 4348.69,1969 8327,1969 8334,1976 8334,2007.31 8345.69,2019 8392,2019 v5(8413,2040)
  Bottom Layer - L10 w8: v5(8413,2040) FMC_RX1.G6@8438,2065
DPDT_1A: DPDT_1A.1 U26.3 U27.1 U30.3 | length 1161.4
  Bottom Layer - L10 w8: U30.3@655.43,1982.68 655.43,1909.57 665,1900 697.04,1900 795.55,1998.51 DPDT_1A.1@882.48,1998.51 1225.91,1998.51 1278.43,1946 U27.1@1323.43,1946 ; U27.1@1323.43,1945.57 1606.57,1945.57 1616.41,1955.41 U26.3@1616.41,2012.14
DPDT_1B: DPDT_1B.1 U26.5 U27.2 U31.3 | length 1612.6
  Bottom Layer - L10 w8: U31.3@655.43,2282.68 655.43,2209.57 665,2200 687.48,2200 787.48,2100 DPDT_1B.1@882.48,2100 950.03,2032.45 1510.45,2032.45 1529,2051 1653.73,2051 1667.59,2037.14 U26.5@1667.59,2012.14 1667.59,1955.41 1632.16,1919.98 U27.2@1323.43,1919.98
DPDT_2A: C345.2 DPDT_2A.1 U26.9 U27.3 U38.3 | length 1494.6
  Bottom Layer - L10 w8: U27.3@1323.43,1894.39 1693.18,1894.39 ; U26.9@1693.18,1779.86 1693.18,1894.39 ; U38.3@1967.43,2282.68 1967.43,2321.08 1982.35,2336 2059,2336 2075,2320 DPDT_2A.1@2119.48,2320 ; C345.2@2179.96,2336 2163.96,2320 DPDT_2A.1@2119.48,2320 ; 1693.18,1894.39 1831.79,2033 2067,2033 2090.48,2056.48 2090.48,2291 DPDT_2A.1@2119.48,2320
DPDT_2B: C341.2 DPDT_2B.1 U26.11 U27.4 U32.3 | length 2121.3
  Top Layer L1 w8: DPDT_2B.1@2119.48,2620 2052,2552.52 2052,2454 2090,2416 2090,2365 2061,2336 2061,2304 2127,2238 v2(2127,2084)
  Bottom Layer - L10 w8: U27.4@1323.43,1868.8 1609.8,1868.8 1642,1836.59 U26.11@1642,1779.86 1642,1723.13 1674.2,1690.92 1947.92,1690.92 2070,1813 2070,1981 2127,2038 v2(2127,2084) ; U32.3@1967.43,2582.68 1967.43,2621.08 1982.35,2636 2059,2636 2075,2620 DPDT_2B.1@2119.48,2620 2163.96,2620 C341.2@2179.96,2636
DPDT_3A: C343.2 DPDT_3A.1 U26.13 U27.5 U36.3 | length 1505.4
  Top Layer L1 w8: DPDT_3A.1@1271.48,2620 1204,2552.52 1204,2454 1242,2416 1242,2365 1204,2327 1204,2154 1242,2116 1242,1886.34 v2(1285.13,1843.2)
  Bottom Layer - L10 w8: U36.3@1119.43,2582.68 1119.43,2621.08 1134.35,2636 1211,2636 1227,2620 DPDT_3A.1@1271.48,2620 1315.96,2620 C343.2@1331.96,2636 ; v2(1285.13,1843.2) U27.5@1323.43,1843.2 1584.2,1843.2 1590.82,1836.59 U26.13@1590.82,1779.86
DPDT_3B: C342.2 DPDT_3B.1 U26.1 U29.1 U34.3 | length 1803.3
  Top Layer L1 w8: DPDT_3B.1@1271.48,2320 1346.96,2320 1368,2298.96 1368,2088 1443.86,2012.14 1545.64,2012.14 1772.86,2012.14 1788.5,1996.5 2416.49,1996.5 v2(2466.99,1946)
  Bottom Layer - L10 w8: U34.3@1119.43,2282.68 1119.43,2321.08 1134.35,2336 1211,2336 1227,2320 DPDT_3B.1@1271.48,2320 1315.96,2320 C342.2@1331.96,2336 ; v2(1544.64,2012.14) U26.1@1565.23,2012.14 ; v2(2466.99,1946) U29.1@2505.28,1946
DPDT_4A: DPDT_4A.1 U29.2 U35.3 U41.6 | length 1525.8
  Top Layer L1 w8: DPDT_4A.1@1606,2319.8 1606,2224.5 1810,2020.5 2539.52,2020.5 v2(2572.45,1987.58)
  Bottom Layer - L10 w8: U35.3@1496.43,2282.68 1496.43,2321.08 1511.35,2336 1545.52,2336 1561.52,2320 DPDT_4A.1@1606,2320 ; DPDT_4A.1@1606,2319.8 1642.48,2319.8 1672.58,2349.9 U41.6@1672.58,2366.4 ; U29.2@2505.28,1920.41 2530.28,1920.41 2572.45,1962.58 v2(2572.45,1987.58)
DPDT_4B: DPDT_4B.1 U29.3 U37.3 U41.1 U41.3 | length 1901.7
  Top Layer L1 w8: DPDT_4B.1@1606,2500 1665.5,2440.5 1665.5,2210.5 1831.5,2044.5 2566.71,2044.5 v2(2623.63,1987.58)
  Bottom Layer - L10 w8: U37.3@1496.43,2582.68 1496.43,2509.57 1506,2500 DPDT_4B.1@1606,2500 1642.48,2500 U41.1@1672.58,2469.9 ; U41.1@1672.58,2453.4 U41.1@1672.58,2469.9 ; U41.3@1724.58,2453.4 1724.58,2469.9 1706.48,2488 1690.68,2488 U41.1@1672.58,2469.9 ; U29.3@2505.28,1894.82 2555.87,1894.82 2623.63,1962.58 v2(2623.63,1987.58)
DPDT_5A: DPDT_5A.1 U29.4 U33.3 | length 1117.9
  Bottom Layer - L10 w8: U33.3@2344.43,2582.68 2344.43,2621.08 2359.35,2636 2393.52,2636 2409.52,2620 DPDT_5A.1@2454,2620 2674.81,2399.19 2674.81,1962.58 2581.46,1869.23 U29.4@2505.28,1869.23
DPDT_5B: DPDT_5B.1 U29.5 U39.3 | length 899.8
  Top Layer L1 w8: DPDT_5B.1@2454,2320 2725.99,2048.01 v2(2725.99,1987.58)
  Bottom Layer - L10 w8: U39.3@2345.43,2282.68 2345.43,2321.08 2360.35,2336 2393.52,2336 2409.52,2320 DPDT_5B.1@2454,2320 ; U29.5@2505.28,1843.64 2607.05,1843.64 2725.99,1962.58 v2(2725.99,1987.58)
EE_ADDR0_RX: FMC_RX1.C34 U16.1 | length 1233.2
  Top Layer L1 w8: U16.1@7435.86,690 v1(7491.16,690)
  Signals - L3 w4: v1(7491.16,690) 7516.16,665 8588,665 v5(8613,690)
  Bottom Layer - L10 w8: v5(8613,690) FMC_RX1.C34@8638,665
EE_ADDR1_RX: FMC_RX1.D35 U16.2 | length 1325.6
  Top Layer L1 w8: U16.2@7435.86,740 v1(7491.16,740)
  Signals - L3 w4: v1(7491.16,740) 7516.17,715 8625,715 8638,702 8638,665 v5(8613,640)
  Bottom Layer - L10 w8: FMC_RX1.D35@8588,615 v5(8613,640)
FMC_ADC_CLK: FMC_RX1.H37 R58.2 | length 1096.2
  Signals - L8 w4: v1(7354.56,515) 7404.56,565 8338,565 v5(8363,540)
  Bottom Layer - L10 w8: R58.2@7354.56,493.62 v1(7354.56,515) ; v5(8363,540) FMC_RX1.H37@8388,515
FMC_ADC_SCSB0: FMC_RX1.H38 R54.2 | length 1128.1
  Signals - L8 w4: v1(7354.56,236.38) 7389.38,236.38 7418,265 8051,265 8201,415 8338,415 v5(8363,440)
  Bottom Layer - L10 w8: v5(8363,440) FMC_RX1.H38@8388,465
FMC_ADC_SDI: FMC_RX1.G36 R57.2 | length 1200.7
  Signals - L8 w4: v1(7299.44,515) 7349.44,465 8151,465 8201,515 8388,515 v5(8413,540)
  Bottom Layer - L10 w8: v5(8413,540) FMC_RX1.G36@8438,565
FMC_ADC_SDO: FMC_RX1.G37 R55.2 | length 1269.8
  Signals - L8 w4: v1(7299.44,236.38) 7325.06,262 7356,262 7399,305 7399,332 7432,365 8101,365 8201,465 8388,465 v5(8413,490)
  Bottom Layer - L10 w8: v5(8413,490) FMC_RX1.G37@8438,515
FMC_DEVCLK_N: C93.2 FMC_RX1.K29 | length 4941.1
  Signals - L6 w4: v1(3948.84,1507.44) 3948.84,1489.67 3966.56,1471.95 4049.63,1471.95 4077.08,1444.5 4077.08,1190.03 4108.11,1159 4469.31,1159 4521,1107.31 4521,1036.2 4545.2,1012 5121.99,1012 5128.99,1019 5832,1019 5882,969 6599,969 6649,919 7199,919 7249,869 8277,869 8284,876 8284,923 8267,940 v5(8263,940)
  Bottom Layer - L10 w8: C93.2@3927.57,1507.44 v1(3948.84,1507.44) ; v5(8263,940) FMC_RX1.K29@8288,915
FMC_DEVCLK_P: C92.2 FMC_RX1.K28 | length 4941.6
  Signals - L6 w4: v1(3948.84,1428.47) 3984.32,1463.95 4046.31,1463.95 4069.08,1441.18 4069.08,1186.71 4104.8,1151 4466,1151 4513,1104 4513,1032.89 4541.89,1004 5125.3,1004 5132.3,1011 5828.69,1011 5878.69,961 6595.69,961 6645.69,911 7195.69,911 7245.69,861 8280.31,861 8292,872.69 8292,919 v5(8313,940)
  Bottom Layer - L10 w8: C92.2@3927.57,1428.47 v1(3948.84,1428.47) ; FMC_RX1.K28@8288,965 v5(8313,940)
FMC_SCL: FMC_RX1.C30 J1.2 R127.2 U16.6 | length 2740.7
  Top Layer L1 w8: J1.2@7046,740 7096,790 U16.6@7168.14,790 7201.2,790 v1(7251.2,840)
  Signals - L3 w4: v1(7251.2,840) 7276.2,865 8588,865 v5(8613,890)
  Bottom Layer - L10 w8: R127.2@6363.68,397.13 6408,441.45 6408,730 6518,840 6946,840 J1.2@7046,740 ; v5(8613,890) FMC_RX1.C30@8638,865
FMC_SDA: FMC_RX1.C31 J1.1 R126.2 U16.5 | length 2673.6
  Top Layer L1 w8: R126.2@6308.56,445 6308.56,657.56 6491,840 J1.1@7046,840 ; U16.5@7168.14,840 v1(7168.14,865)
  Signals - L8 w4: J1.1@7046,840 7071,865 8588,865 v5(8613,840)
  Bottom Layer - L10 w8: v5(8613,840) FMC_RX1.C31@8638,815
FMC_SPI_CLK: FMC_RX1.G30 R121.2 | length 2425
  Signals - L8 w4: v1@6626.99,789.01 7086.01,789.01 7112,815 8388,815 v5(8413,840)
  Bottom Layer - L10 w8: R121.2@6547.56,240 6626,318.44 v1(6626,790) ; v5(8413,840) FMC_RX1.G30@8438,865
FMC_SPI_SCSB1: FMC_RX1.G33 R69.2 | length 2004.3
  Signals - L8 w4: v1(6578,470.44) 6597.56,490 7123,490 7298,665 8388,665 v5(8413,690)
  Bottom Layer - L10 w8: R69.2@6547.56,440 v1(6578,470.44) ; v5(8413,690) FMC_RX1.G33@8438,715
FMC_SPI_SCSB2: FMC_RX1.G34 R119.2 | length 2062.9
  Signals - L8 w4: v1(6547.56,590) 7150,590 7275,715 8438,715 v5(8463,690)
  Bottom Layer - L10 w8: R119.2@6547.56,540 v1(6547.56,590) ; FMC_RX1.G34@8438,665 v5(8463,690)
FMC_SPI_SDIO: FMC_RX1.H34 R120.2 | length 1975.1
  Signals - L8 w4: v1(6602,390) 7088,390 7313,615 8338,615 v5(8363,640)
  Bottom Layer - L10 w8: R120.2@6547.56,340 6552,340 v1(6602,390) ; v5(8363,640) FMC_RX1.H34@8388,665
FMC_SYSREF_N: C91.2 FMC_RX1.K38 | length 5456.4
  Signals - L6 w4: v1(4148.96,1720.97) 4158.96,1710.97 4158.96,1647 4138.35,1626.39 4138.35,1233.09 4150.47,1220.97 4427.83,1220.97 4454.63,1194.16 4485.25,1194.16 4535.42,1144 5110.62,1144 5185.61,1069 6203,1069 6253,1019 6627,1019 6677,969 8330.31,969 8342,957.31 8342,472.69 8330.31,461 8284,461 v5(8263,440)
  Bottom Layer - L10 w8: C91.2@4142.94,1697.99 4142.94,1714.94 v1(4148.96,1720.97) ; v5(8263,440) FMC_RX1.K38@8288,465
FMC_SYSREF_P: C90.2 FMC_RX1.K37 | length 5456.2
  Signals - L6 w4: v1(4097.93,1715.99) 4099.9,1714.02 4099.9,1656.84 4130.35,1626.39 4130.35,1229.77 4147.16,1212.97 4424.51,1212.97 4451.32,1186.16 4481.94,1186.16 4532.1,1136 5107.3,1136 5182.3,1061 6199.69,1061 6249.69,1011 6623.69,1011 6673.69,961 8327,961 8334,954 8334,476 8327,469 8263,469 8257,475 8257,484 v5(8263,490)
  Bottom Layer - L10 w8: v1(4097.93,1715.99) C90.2@4115.93,1697.99 ; v5(8263,490) FMC_RX1.K37@8288,515
FTDI_ADC_SCLK: R109.2 U12.14 | length 122.5
  Top Layer L1 w8: U12.14@7191.24,403.91 7260.85,403.91 7295.44,438.5 R109.2@7299.44,438.5
FTDI_ADC_SCSB: R118.2 R123.1 U12.11 | length 123
  Top Layer L1 w8: U12.11@7191.24,327.14 7241.94,327.14 R123.1@7251,318.09 7262.56,306.53 7284.41,306.53 R118.2@7299.44,291.5
FTDI_ADC_SDI: R111.2 U12.13 | length 112.8
  Top Layer L1 w8: U12.13@7191.24,378.32 7288.26,378.32 R111.2@7299.44,389.5
FTDI_ADC_SDO: R110.2 U12.12 | length 113.3
  Top Layer L1 w8: U12.12@7191.24,352.73 7287.21,352.73 R110.2@7299.44,340.5
FTDI_LMK_CSB: R68.2 R130.2 U13.40 | length 347.3
  Top Layer L1 w8: U13.40@6147.98,478.16 6214.45,478.16 v1(6219.44,483.16) ; v1(6364.88,440) R68.2@6389.88,440
  Signals - L6 w4: v1(6219.44,483.16) 6321.72,483.16 v1(6364.88,440)
  Bottom Layer - L10 w8: v1(6219.44,483.16) 6288.25,483.16 R130.2@6300,494.9
FTDI_LMK_TRF_CLK: R115.2 U13.38 | length 494.8
  Top Layer L1 w8: U13.38@6147.98,438.79 6202.45,438.79 v1(6207.44,433.79) ; R115.2@6437.32,157.56 v1(6437.32,198)
  Signals - L6 w4: v1(6207.44,433.79) 6196,422.34 6196,350 6249,297 6321,297 6374,244 6391.32,244 v1(6437.32,198)
FTDI_LMK_TRF_DATA: R114.2 U13.39 | length 314.3
  Top Layer L1 w8: U13.39@6147.98,458.47 6214.45,458.47 v1(6219.44,453.47) ; v1(6364.88,298) R114.2@6389.88,298
  Signals - L6 w4: v1(6219.44,453.47) 6364.88,308.04 v1(6364.88,298)
FTDI_TRF_R1: U4.6 U13.43 | length 2136.4
  Top Layer L1 w8: U4.6@5396.71,1884.49 v1(5396.71,1940) ; v1(6128,915) 6223,915 6296,842 6296,748 6197,649 6197,551 6183.21,537.21 U13.43@6147.98,537.21
  Signals - L3 w4: v1(5396.71,1940) 5367.18,1910.47 5367.18,1430.82 5555,1243 5725,1243 6053,915 v1(6128,915)
FTDI_TRF_STROBE: R113.2 R131.2 U13.41 | length 308.3
  Top Layer L1 w8: U13.41@6147.98,497.84 6202.45,497.84 v1(6207.44,502.84) ; v1(6365.44,540) R113.2@6390.44,540
  Signals - L6 w4: v1(6207.44,502.84) 6328.28,502.84 v1(6365.44,540)
  Bottom Layer - L10 w8: v1(6207.44,502.84) 6239.25,502.84 R131.2@6251,514.59
FTDI_TS_SMBCLK: R125.2 U13.26 | length 552.5
  Top Layer L1 w8: v1(5952,189.03) 5959,196.03 U13.26@5959,269.5
  Bottom Layer - L10 w8: v1(5952,189.03) 5959,196.03 5959,245 5995,281 6157,281 6242.77,366.77 6283.8,366.77 v1(6308.56,342.01)
FTDI_TS_SMBDAT_IN: R124.2 U13.28 | length 365.7
  Top Layer L1 w8: v1(5998.37,215.03) U13.28@5998.37,269.5
  Bottom Layer - L10 w8: v1(5998.37,215.03) 6034.34,251 6165.99,251 v1(6257,342.01)
FTDI_TS_SMBDAT_OUT: R117.2 U18.4 | length 302.4
  Bottom Layer - L10 w8: U18.4@5921.29,430.85 5921.29,439.29 5967,485 6087,485 6126.7,445.3 R117.2@6126.7,392.13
